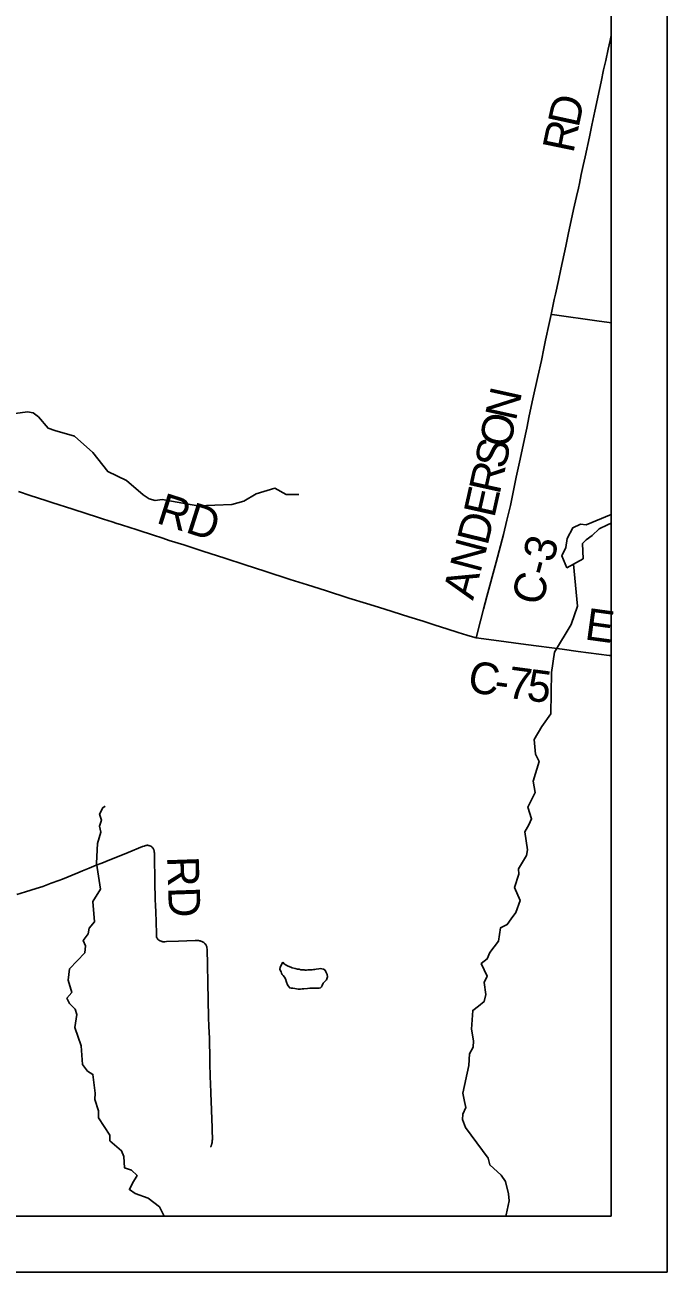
# Model space of a CAD drawing. Extents: x -19.5 to 44.1, y 0 to 22.
# Drawn here: x -13.464 to -12.313, y 14 to 16.235 of the extents above; entities that cross this region are included whole.
import ezdxf

# ---------------------------------------------------------------- set-up
doc = ezdxf.new("R2010")
doc.units = 0
for name, color, linetype in [('GM_X_County_Road', 7, 'Continuous'), ('GM_X_County_Road_Text', 7, 'Continuous'), ('GM_X_Minor_Lake', 7, 'Continuous'), ('GM_X_Minor_River', 7, 'Continuous'), ('GM_X_Township_Road', 7, 'Continuous'), ('GM_X_Township_Road_Text', 7, 'Continuous'), ('SH_Data', 7, 'Continuous')]:
    doc.layers.add(name, color=color, linetype=linetype)

msp = doc.modelspace()

# ---------------------------------------------------------------- linework, layer by layer
at = {"layer": 'GM_X_County_Road'}
for points in [[(-12.5211, 15.7164), (-12.5152, 15.7433), (-12.5131, 15.7524), (-12.5078, 15.7773), (-12.5034, 15.7973), (-12.4946, 15.8386), (-12.4902, 15.8593), (-12.4806, 15.9042), (-12.4753, 15.9279), (-12.4721, 15.9425), (-12.4703, 15.951), (-12.4668, 15.9673), (-12.4634, 15.9831), (-12.4599, 15.9989), (-12.452, 16.0347), (-12.4478, 16.0554), (-12.4427, 16.0803), (-12.4344, 16.1192), (-12.4314, 16.1332), (-12.4268, 16.1544), (-12.4231, 16.1713), (-12.4186, 16.1919), (-12.415, 16.2074), (-12.413, 16.2159)], [(-12.6552, 15.1368), (-12.6475, 15.1671), (-12.642, 15.1881), (-12.6359, 15.2108), (-12.6194, 15.272), (-12.6063, 15.3219), (-12.6001, 15.3473), (-12.594, 15.3738), (-12.5895, 15.3946), (-12.5833, 15.4246), (-12.5766, 15.4566), (-12.567, 15.5016), (-12.5647, 15.5125), (-12.56, 15.5344), (-12.5535, 15.5648), (-12.5447, 15.6048), (-12.5383, 15.6339), (-12.5338, 15.6552), (-12.5307, 15.6704), (-12.5246, 15.7002), (-12.5211, 15.7164)], [(-12.5211, 15.7164), (-12.5149, 15.7154), (-12.4897, 15.7117), (-12.4639, 15.7081), (-12.4387, 15.7047), (-12.4171, 15.7019), (-12.413, 15.7013)], [(-13.4755, 15.3987), (-13.4548, 15.392), (-13.427, 15.3829), (-13.4158, 15.3792), (-13.3786, 15.3674), (-13.3325, 15.3524), (-13.3236, 15.3495), (-13.3076, 15.3444), (-13.2993, 15.3418), (-13.2929, 15.3397), (-13.2858, 15.3373), (-13.2817, 15.336), (-13.2592, 15.3288), (-13.2355, 15.3211), (-13.2172, 15.3151), (-13.2054, 15.3114), (-13.1793, 15.3032), (-13.1687, 15.2998), (-13.145, 15.2921), (-13.106, 15.2795), (-13.0694, 15.2675), (-13.0339, 15.256), (-12.9884, 15.2414), (-12.9576, 15.2314), (-12.9256, 15.2214), (-12.8836, 15.2079), (-12.8521, 15.1982), (-12.8379, 15.1939), (-12.8189, 15.1879), (-12.7757, 15.1742), (-12.7502, 15.1663), (-12.7289, 15.1594), (-12.7076, 15.1526), (-12.6876, 15.1461), (-12.6796, 15.1436), (-12.672, 15.1413), (-12.666, 15.1396), (-12.6552, 15.1368)], [(-12.6552, 15.1368), (-12.6236, 15.1322), (-12.5664, 15.1245), (-12.5011, 15.1161), (-12.4722, 15.1123), (-12.4168, 15.1053), (-12.413, 15.1049)]]:
    msp.add_lwpolyline(points, dxfattribs=at)
at = {"layer": 'GM_X_Minor_Lake'}
for points in [[(-12.413, 15.3579), (-12.4579, 15.3392), (-12.4685, 15.3406), (-12.4819, 15.334), (-12.4922, 15.3149), (-12.4948, 15.2986), (-12.5016, 15.2836), (-12.4925, 15.2621)], [(-12.4634, 15.2781), (-12.4647, 15.3055), (-12.4581, 15.3122), (-12.4473, 15.3199), (-12.4345, 15.3322), (-12.4199, 15.3394), (-12.413, 15.3424)], [(-12.4925, 15.2621), (-12.4634, 15.2781)], [(-13.002, 14.5554), (-12.9986, 14.552), (-12.9936, 14.5489), (-12.9895, 14.547), (-12.9876, 14.5462), (-12.9849, 14.5454), (-12.9796, 14.5442), (-12.9758, 14.5431), (-12.9724, 14.5426), (-12.9697, 14.5419), (-12.9678, 14.5415), (-12.9659, 14.5415), (-12.9637, 14.5414), (-12.9618, 14.541), (-12.9595, 14.541), (-12.9568, 14.5414), (-12.9545, 14.5414), (-12.9522, 14.5414), (-12.9492, 14.5417), (-12.9469, 14.5421), (-12.9446, 14.5424), (-12.9423, 14.5428), (-12.9374, 14.5435), (-12.9351, 14.5439), (-12.9317, 14.5435), (-12.9287, 14.5431), (-12.926, 14.5408), (-12.9245, 14.5381), (-12.9234, 14.5354), (-12.9226, 14.5332), (-12.9219, 14.5294), (-12.9223, 14.5275), (-12.9238, 14.524), (-12.9254, 14.5218), (-12.9273, 14.5199), (-12.9296, 14.5176), (-12.9315, 14.5135), (-12.9323, 14.5112), (-12.9346, 14.5093), (-12.9369, 14.5089), (-12.9403, 14.509), (-12.9445, 14.509), (-12.9487, 14.509), (-12.9532, 14.5087), (-12.9578, 14.5079), (-12.9639, 14.5076), (-12.9673, 14.5076), (-12.9703, 14.5073), (-12.9722, 14.5073), (-12.9741, 14.5073), (-12.9772, 14.5077), (-12.9806, 14.5081), (-12.984, 14.5085), (-12.9871, 14.5089), (-12.9893, 14.5093), (-12.992, 14.5128), (-12.9935, 14.5147), (-12.9954, 14.5196), (-12.9968, 14.5253), (-12.9991, 14.5284), (-13.0014, 14.5315), (-13.0029, 14.5334), (-13.004, 14.5357), (-13.0051, 14.5379), (-13.0063, 14.5399), (-13.007, 14.5429), (-13.0066, 14.5456), (-13.0062, 14.5478), (-13.002, 14.5554)]]:
    msp.add_lwpolyline(points, dxfattribs=at)
at = {"layer": 'GM_X_Minor_River'}
for points in [[(-13.4816, 15.5387), (-13.4595, 15.5416), (-13.4497, 15.5399), (-13.44, 15.5328), (-13.4226, 15.5126), (-13.4105, 15.5082), (-13.3754, 15.4982), (-13.3423, 15.469), (-13.3157, 15.4345), (-13.2819, 15.4185), (-13.2525, 15.3932), (-13.2412, 15.3857), (-13.2307, 15.3828), (-13.2181, 15.3844), (-13.1542, 15.3734), (-13.0935, 15.3754), (-13.0717, 15.3817), (-13.0498, 15.3945), (-13.0162, 15.4047), (-12.9956, 15.3936), (-12.9732, 15.3938)], [(-12.6013, 14.1), (-12.6016, 14.1024), (-12.5961, 14.1278), (-12.5973, 14.1403), (-12.6026, 14.1625), (-12.6103, 14.1737), (-12.6308, 14.192), (-12.6335, 14.2039), (-12.6745, 14.2592), (-12.6795, 14.2737), (-12.6793, 14.2832), (-12.6737, 14.2949), (-12.6761, 14.3059), (-12.6789, 14.3204), (-12.6683, 14.3704), (-12.6675, 14.3912), (-12.6608, 14.4032), (-12.6598, 14.4142), (-12.6635, 14.4356), (-12.6613, 14.469), (-12.6512, 14.4767), (-12.6412, 14.4848), (-12.6379, 14.4973), (-12.6412, 14.519), (-12.6357, 14.5303), (-12.6462, 14.553), (-12.6354, 14.5611), (-12.631, 14.5728), (-12.6154, 14.5933), (-12.6114, 14.6171), (-12.5996, 14.6226), (-12.5925, 14.633), (-12.5839, 14.6442), (-12.5766, 14.6661), (-12.5864, 14.6891), (-12.579, 14.7129), (-12.5792, 14.7224), (-12.565, 14.7464), (-12.5633, 14.7566), (-12.5679, 14.789), (-12.5608, 14.8017), (-12.556, 14.8123), (-12.5628, 14.8333), (-12.5493, 14.8592), (-12.5531, 14.8798), (-12.5425, 14.9149), (-12.5486, 14.9283), (-12.5511, 14.9542), (-12.5373, 14.9775), (-12.5217, 15.0007), (-12.5201, 15.0743), (-12.5151, 15.1107), (-12.4852, 15.1605), (-12.4735, 15.1933), (-12.4805, 15.2688)], [(-13.2145, 14.1), (-13.2232, 14.117), (-13.2433, 14.1327), (-13.2663, 14.1408), (-13.2768, 14.1479), (-13.2712, 14.1592), (-13.263, 14.173), (-13.2734, 14.1824), (-13.2858, 14.1869), (-13.2869, 14.2074), (-13.2909, 14.2174), (-13.3117, 14.2354), (-13.3119, 14.2453), (-13.3325, 14.2765), (-13.3322, 14.289), (-13.339, 14.309), (-13.3384, 14.3204), (-13.3422, 14.3543), (-13.3519, 14.3602), (-13.3612, 14.3718), (-13.3635, 14.4053), (-13.3746, 14.4382), (-13.371, 14.4613), (-13.3739, 14.4709), (-13.3843, 14.4814), (-13.389, 14.491), (-13.3801, 14.5011), (-13.3868, 14.5229), (-13.3841, 14.5437), (-13.3569, 14.5719), (-13.3555, 14.5844), (-13.3598, 14.5944), (-13.3509, 14.606), (-13.3488, 14.6162), (-13.3394, 14.6274), (-13.3424, 14.6643), (-13.3287, 14.6864), (-13.3356, 14.7329), (-13.3341, 14.7678), (-13.328, 14.7886), (-13.3304, 14.7989), (-13.3272, 14.8098), (-13.3303, 14.8206), (-13.3248, 14.8322), (-13.3202, 14.8351)]]:
    msp.add_lwpolyline(points, dxfattribs=at)
at = {"layer": 'GM_X_Township_Road'}
for points in [[(-13.4789, 14.6766), (-13.463, 14.6816), (-13.4443, 14.6875), (-13.4322, 14.6913), (-13.417, 14.6969), (-13.4036, 14.7018), (-13.3967, 14.7043), (-13.3695, 14.7154), (-13.3609, 14.7189), (-13.3491, 14.7239), (-13.3364, 14.729), (-13.3266, 14.7329), (-13.3119, 14.7387), (-13.2953, 14.7452), (-13.2794, 14.7517), (-13.2532, 14.7624), (-13.2504, 14.7635), (-13.2492, 14.7639), (-13.2484, 14.7641), (-13.2478, 14.7643), (-13.2465, 14.7646), (-13.2454, 14.7648), (-13.2444, 14.7648), (-13.2435, 14.7647), (-13.2425, 14.7646), (-13.2415, 14.7643), (-13.2406, 14.7641), (-13.2397, 14.7638), (-13.2388, 14.7634), (-13.238, 14.763), (-13.2373, 14.7624), (-13.2365, 14.7618), (-13.2358, 14.7611), (-13.2351, 14.7602), (-13.2343, 14.7591), (-13.2338, 14.7582), (-13.2333, 14.7573), (-13.2329, 14.7562), (-13.2326, 14.7553), (-13.2324, 14.754), (-13.2322, 14.7527), (-13.2321, 14.7512), (-13.232, 14.749), (-13.2318, 14.7325), (-13.2316, 14.7132), (-13.2313, 14.694), (-13.2307, 14.6729), (-13.2305, 14.6662), (-13.2301, 14.6587), (-13.2294, 14.6436), (-13.2289, 14.6296), (-13.2286, 14.6044), (-13.2284, 14.6021), (-13.2281, 14.6007), (-13.2276, 14.5991), (-13.2268, 14.5977), (-13.2263, 14.5969), (-13.2256, 14.596), (-13.2242, 14.5949), (-13.2228, 14.5941), (-13.2215, 14.5934), (-13.2201, 14.5928), (-13.219, 14.5925), (-13.2181, 14.5923), (-13.217, 14.5921), (-13.2158, 14.5921), (-13.2147, 14.5921), (-13.2134, 14.5921), (-13.2106, 14.5922), (-13.1886, 14.593), (-13.1588, 14.5941), (-13.1573, 14.5942), (-13.1557, 14.5942), (-13.1542, 14.5941), (-13.1528, 14.594), (-13.1514, 14.5939), (-13.1502, 14.5936), (-13.1489, 14.5933), (-13.1472, 14.5926), (-13.1456, 14.5918), (-13.1446, 14.5912), (-13.1436, 14.5905), (-13.1427, 14.5898), (-13.1419, 14.589), (-13.1409, 14.5879), (-13.1401, 14.5869), (-13.1395, 14.5859), (-13.139, 14.5849), (-13.1387, 14.5839), (-13.1383, 14.5826), (-13.138, 14.5813), (-13.1377, 14.5789), (-13.1367, 14.5504), (-13.1361, 14.5182), (-13.1348, 14.457), (-13.1342, 14.4403), (-13.1335, 14.4189), (-13.1333, 14.4073)], [(-13.1333, 14.4073), (-13.133, 14.3925), (-13.1326, 14.3761), (-13.1321, 14.3488), (-13.1318, 14.3393), (-13.1311, 14.3202), (-13.1306, 14.3061), (-13.1298, 14.2902), (-13.1288, 14.2587), (-13.1285, 14.2504), (-13.1282, 14.2424), (-13.1282, 14.2399), (-13.1282, 14.2378), (-13.1283, 14.2357), (-13.1284, 14.2345), (-13.1285, 14.2332), (-13.1287, 14.232), (-13.1289, 14.2307), (-13.1291, 14.2296), (-13.1293, 14.229), (-13.1295, 14.2284), (-13.1298, 14.2274), (-13.1301, 14.2266), (-13.1304, 14.2259), (-13.1307, 14.2253), (-13.1311, 14.2247), (-13.1315, 14.224)]]:
    msp.add_lwpolyline(points, dxfattribs=at)
at = {"layer": 'SH_Data'}
for p, q in [((-12.313, 21), (-12.313, 14)), ((-12.413, 20.9), (-12.413, 14.1)), ((-19.213, 14.1), (-12.413, 14.1)), ((-19.313, 14), (-12.313, 14))]:
    msp.add_line(p, q, dxfattribs=at)

# ---------------------------------------------------------------- texts
at = {"layer": 'GM_X_County_Road_Text'}
for s, height, rotation, p in [('D', 0.0568, 77.7248, (-12.4718, 16.0495)), ('R', 0.0568, 78.3357, (-12.4812, 16.0039)), ('N', 0.0568, 77.5297, (-12.5843, 15.5238)), ('O', 0.0568, 77.5312, (-12.5951, 15.475)), ('S', 0.0568, 77.5335, (-12.6034, 15.4375)), ('R', 0.0568, 77.5325, (-12.6134, 15.392)), ('E', 0.0568, 77.3532, (-12.6228, 15.3503)), ('RD', 0.05682, 342.3264, (-13.2307, 15.3431)), ('D', 0.0568, 76.2168, (-12.635, 15.3005)), ('N', 0.0568, 75.1778, (-12.6481, 15.2511)), ('C-3', 0.05682, 75.1859, (-12.538, 15.1922)), ('A', 0.0568, 75.0674, (-12.661, 15.2027)), ('E', 0.0568, 352.1845, (-12.4622, 15.1341)), ('C', 0.0568, 350.5845, (-12.6724, 15.0407)), ('7', 0.0568, 352.4257, (-12.6013, 15.0295)), ('5', 0.0568, 352.5432, (-12.5664, 15.0249)), ('-', 0.0568, 352.0202, (-12.6248, 15.0328))]:
    msp.add_text(s, height=height, rotation=rotation, dxfattribs=at).set_placement(p)
at = {"layer": 'GM_X_Township_Road_Text'}
msp.add_text('RD', height=0.05682, rotation=271.9739, dxfattribs=at).set_placement((-13.2095, 14.7444))

doc.saveas('drawing.dxf')
